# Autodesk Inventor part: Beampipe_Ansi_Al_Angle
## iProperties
Shininess: 64.0
Length Units: 11272
Angle Units: 11279
Time Units: 11290
Mass Units: 11286
Length Display Precision: 3
Angle Display Precision: 2
Compacted: True
Part Number: Beampipe_Ansi_Al_Angle
Document SubType Name: Modeling
Created: 2004-08
Designer: John Blackburn
Manufacturer: Standard
Standards Organization: Custom
Material: Aluminum-6061
Density: 0.0
Volumn: 0.0
Area: 0.0
PropertySet Name: Model Information
Control State: 0
Master: False
Checked Out: False
Author: John Blackburn
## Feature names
1. Extrusion1
2. Extrusion2
3. Extrusion6
